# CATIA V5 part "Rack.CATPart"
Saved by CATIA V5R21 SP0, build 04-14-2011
Part number: Part2
Bounding box of the stored display mesh (mm): x -50 to 50, y -15 to 20, z 15 to 70
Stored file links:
  D:\CATIA V5R21 E-RESOURCES\CATIA-V5R21\catia-v5r21-Prts\c16_catia_v5r21_prt\Rack Joint-(Fig16-57)\Rack.CATPart
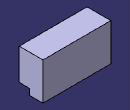
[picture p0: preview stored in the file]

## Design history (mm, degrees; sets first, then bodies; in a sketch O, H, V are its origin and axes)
Body1 (main body)
  Sketch1 on yz-plane, origin (0, 0, 0), H (0, 1, 0), V (0, 0, 1)
    line L1 (0, 15) -> (20, 15)
    point P1 (0, 15)
    reference intersected line E1 through (0, 0) direction (-1, 0) from xy-plane
    reference intersected line E3 through (0, 0) direction (0, 1) from zx-plane
    reference intersected line E4 through (0, 0) direction (-1, 0) from xy-plane
    reference intersected line E6 through (0, 0) direction (0, 1) from zx-plane
    point P3 (20, 70)
    line L2 (20, 70) -> (-15, 70)
    point P4 (-15, 70)
    reference intersected line E7 through (0, 0) direction (-1, 0) from xy-plane
    reference intersected line E9 through (0, 0) direction (0, 1) from zx-plane
    line L3 (20, 15) -> (20, 70)
    line L4 (-15, 70) -> (-15, 24)
    line L5 (-15, 24) -> (0, 24)
    point P6 (0, 24)
    line L6 (0, 15) -> (0, 24)
    distance E1 L1 = 15
    distance H L2 = 70
    distance P3 P4 = 35
    length L1 = 20
    length L6 = 9
    horizontal: L1 H, E1 H, E4 H, L2 H, E7 H, L5 H
    vertical: E3 V, E6 V, E9 V, L3 V, L4 V, L6 V
    coincidence: P1 V, P6 V
  Pad1: profile Sketch1, direction (1, 0, 0), length 50, mirrored extent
